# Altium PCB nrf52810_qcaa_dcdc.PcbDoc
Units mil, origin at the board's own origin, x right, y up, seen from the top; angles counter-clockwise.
Board outline 618 x 551 mil, 2 copper layers (Top Layer, Bottom Layer), stack 65.8 mil thick; 19 components, 31 nets, 72 pads, 43 vias.
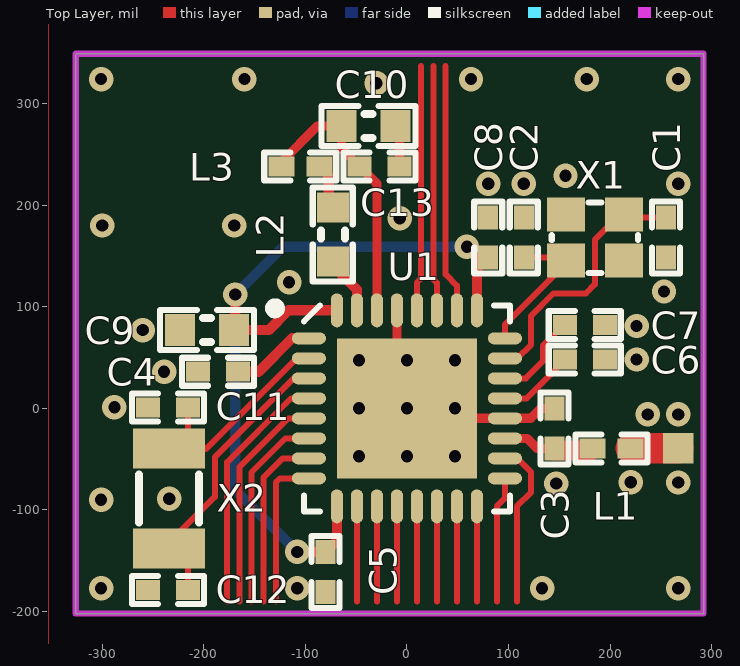
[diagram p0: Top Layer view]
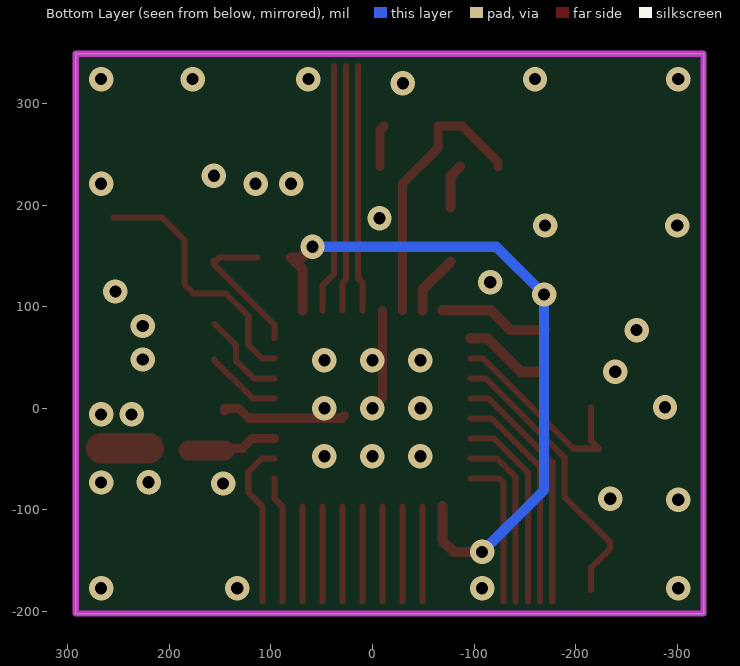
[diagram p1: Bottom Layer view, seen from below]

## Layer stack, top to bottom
Top Solder: solder mask 0.4, Solder Resist, Dk 3.5
Top Layer: signal copper 1.4
Dielectric1: core 63, FR-4, Dk 4.8
Bottom Layer: signal copper 1.4
Bottom Solder: solder mask 0.4, Solder Resist, Dk 3.5

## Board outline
-326,-202 292,-202 292,349 -326,349

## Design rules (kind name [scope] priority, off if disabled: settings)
AssemblyTestPointUsage [All] p0: scope1count=1 scope1_0_kind=Board scope1_0_value=Board scope2count=1 scope2_0_kind=Board scope2_0_value=Board commentlength=0
AssemblyTestpoint [All] p0: scope1count=1 scope1_0_kind=Board scope1_0_value=Board scope2count=1 scope2_0_kind=Board scope2_0_value=Board commentlength=0
Clearance Polygon [All] p0 off: scope1count=1 scope1_0_kind=Board scope1_0_value=Board scope2count=1 scope2_0_kind=Board scope2_0_value=Board commentlength=112 gap=10 // Protel DXP Scope 1 Expression Was: (InNamedPolygon('Top_Layer-GND')) or (InNamedPolygon('Bottom_Layer-GND'))
Clearance Polygon_ANT [All] p0 off: scope1count=1 scope1_0_kind=Board scope1_0_value=Board scope2count=1 scope2_0_kind=Net scope2_0_value=RF commentlength=112 gap=5 // Protel DXP Scope 1 Expression Was: (InNamedPolygon('Top_Layer-GND')) or (InNamedPolygon('Bottom_Layer-GND'))
Clearance [All] p0: scope1count=1 scope1_0_kind=Board scope1_0_value=Board scope2count=1 scope2_0_kind=Board scope2_0_value=Board commentlength=0 gap=6
Clearance Polygon_ANT [(InNamedPolygon('Top_Layer-GND')) or (InNamedPolygon('Bottom_Layer-GND')) vs InNet('RF')] p1: gap=5 ignorepadtopadclearanceinfootprint=FALSE except(0: Arc-Hole Track-Hole SMDPad-Hole THPad-Hole Via-Hole Fill-Hole Poly-Hole Region-Hole Text-Hole)
Clearance Polygon [(InNamedPolygon('Top_Layer-GND')) or (InNamedPolygon('Bottom_Layer-GND'))] p2: gap=10 ignorepadtopadclearanceinfootprint=FALSE except(0: Arc-Hole Track-Hole SMDPad-Hole THPad-Hole Via-Hole Fill-Hole Poly-Hole Region-Hole Text-Hole)
Clearance [All] p3: gap=6 ignorepadtopadclearanceinfootprint=FALSE except(0: Arc-Hole Track-Hole SMDPad-Hole THPad-Hole Via-Hole Fill-Hole Poly-Hole Region-Hole Text-Hole)
ComponentClearance [All] p0 off: scope1count=1 scope1_0_kind=Board scope1_0_value=Board scope2count=1 scope2_0_kind=Board scope2_0_value=Board commentlength=0 gap=10 collisioncheckmode=3
ComponentClearance [All] p1 off: gap=10 collisioncheckmode=3 verticalgap=10 showdistances=FALSE
DiffPairsRouting [All] p0: scope1count=1 scope1_0_kind=Board scope1_0_value=Board scope2count=1 scope2_0_kind=Board scope2_0_value=Board commentlength=0
FabricationTestPointUsage TestPointUsage [All] p0: scope1count=1 scope1_0_kind=Board scope1_0_value=Board scope2count=1 scope2_0_kind=Board scope2_0_value=Board commentlength=0 valid=0 allowmultiple=FALSE
FabricationTestPointUsage TestPointUsage [All] p1: valid=0 allowmultiple=FALSE
FabricationTestpoint Testpoint [All] p0: scope1count=1 scope1_0_kind=Board scope1_0_value=Board scope2count=1 scope2_0_kind=Board scope2_0_value=Board commentlength=0 side=3 testpointundercomponent=TRUE minsize=40 maxsize=100 preferedsize=60 minholesize=0 maxholesize=40 preferedholesize=32 testpointgrid=1
FabricationTestpoint Testpoint [All] p1: side=3 testpointundercomponent=TRUE minsize=40 maxsize=100 preferedsize=60 minholesize=0 maxholesize=40 preferedholesize=32 testpointgrid=1 allowsidetop=TRUE allowsidebottom=TRUE usegrid=TRUE gridtolerance=0.01
FanoutControl Fanout_Default [All] p0: scope1count=1 scope1_0_kind=Board scope1_0_value=Board scope2count=1 scope2_0_kind=Board scope2_0_value=Board commentlength=30 // Fanout_Default (Default Rule)
FanoutControl Fanout_Small [All] p0 off: scope1count=1 scope1_0_kind=Board scope1_0_value=Board scope2count=1 scope2_0_kind=Board scope2_0_value=Board commentlength=84 // Protel DXP Scope 1 Expression Was: (CompPinCount < 5)   Fanout_Small (Default Rule)
FanoutControl Fanout_SOIC [All] p0 off: scope1count=1 scope1_0_kind=Board scope1_0_value=Board scope2count=1 scope2_0_kind=Board scope2_0_value=Board commentlength=71 // Protel DXP Scope 1 Expression Was: IsSOIC   Fanout_SOIC (Default Rule)
FanoutControl Fanout_LCC [All] p0 off: scope1count=1 scope1_0_kind=Board scope1_0_value=Board scope2count=1 scope2_0_kind=Board scope2_0_value=Board commentlength=69 // Protel DXP Scope 1 Expression Was: IsLCC   Fanout_LCC (Default Rule)
FanoutControl Fanout_BGA [All] p0 off: scope1count=1 scope1_0_kind=Board scope1_0_value=Board scope2count=1 scope2_0_kind=Board scope2_0_value=Board commentlength=69 // Protel DXP Scope 1 Expression Was: IsBGA   Fanout_BGA (Default Rule)
Height [All] p0 off: scope1count=1 scope1_0_kind=Board scope1_0_value=Board scope2count=1 scope2_0_kind=Board scope2_0_value=Board commentlength=0
Height [All] p1 off: minheight=0 maxheight=1000 prefheight=500
HoleSize [All] p0: scope1count=1 scope1_0_kind=Board scope1_0_value=Board scope2count=1 scope2_0_kind=Board scope2_0_value=Board commentlength=0 absolutevalues=TRUE maxlimit=160 minlimit=12 maxpercent=80.000 minpercent=20.000
HoleSize [All] p1: absolutevalues=TRUE maxlimit=160 minlimit=12 maxpercent=80.000 minpercent=20.000
HoleToHoleClearance [All] p0: scope1count=1 scope1_0_kind=Board scope1_0_value=Board scope2count=1 scope2_0_kind=Board scope2_0_value=Board commentlength=0
LayerPairs [All] p0: scope1count=1 scope1_0_kind=Board scope1_0_value=Board scope2count=1 scope2_0_kind=Board scope2_0_value=Board commentlength=0 enforce=TRUE
MinimumAnnularRing [All] p0 off: scope1count=1 scope1_0_kind=Board scope1_0_value=Board scope2count=1 scope2_0_kind=Board scope2_0_value=Board commentlength=0 minimumring=6
MinimumAnnularRing [All] p1 off: minimumring=6
MinimumSolderMaskSliver [All] p0: scope1count=1 scope1_0_kind=Board scope1_0_value=Board scope2count=1 scope2_0_kind=Board scope2_0_value=Board commentlength=0
NetAntennae [All] p0: scope1count=1 scope1_0_kind=Board scope1_0_value=Board scope2count=1 scope2_0_kind=Board scope2_0_value=Board commentlength=0
PasteMaskExpansion [All] p0: scope1count=1 scope1_0_kind=Board scope1_0_value=Board scope2count=1 scope2_0_kind=Board scope2_0_value=Board commentlength=0 expansion=0
PlaneClearance [All] p0: scope1count=1 scope1_0_kind=Board scope1_0_value=Board scope2count=1 scope2_0_kind=Board scope2_0_value=Board commentlength=0 clearance=20
PlaneConnect [All] p0: scope1count=1 scope1_0_kind=Board scope1_0_value=Board scope2count=1 scope2_0_kind=Board scope2_0_value=Board commentlength=0 planeconnectstyle=Relief reliefexpansion=20 reliefentries=4 reliefconductorwidth=10 reliefairgap=10
PolygonConnect [All] p0: scope1count=1 scope1_0_kind=Board scope1_0_value=Board scope2count=1 scope2_0_kind=Board scope2_0_value=Board commentlength=0 connectstyle=Relief reliefconductorwidth=10 reliefentries=4 polygonreliefangle="90 Angle"
PolygonConnect PolygonConnect_1 [All] p0 off: scope1count=1 scope1_0_kind=Board scope1_0_value=Board scope2count=1 scope2_0_kind=Board scope2_0_value=Board commentlength=59 connectstyle=Direct reliefconductorwidth=10 reliefentries=4 polygonreliefangle="90 Angle" // Protel DXP Scope 1 Expression Was: isVia and innet(gnd)
PolygonConnect PolygonConnect_1 [isVia and innet(gnd)] p1: connectstyle=Direct reliefconductorwidth=10 reliefentries=4 polygonreliefangle="90 Angle" airgapwidth=10
PolygonConnect [All] p2: connectstyle=Relief reliefconductorwidth=10 reliefentries=4 polygonreliefangle="90 Angle" airgapwidth=10
RoutingCorners [All] p0: scope1count=1 scope1_0_kind=Board scope1_0_value=Board scope2count=1 scope2_0_kind=Board scope2_0_value=Board commentlength=0 cornerstyle=45-Degree minsetback=100 maxsetback=100
RoutingLayers [All] p0: scope1count=1 scope1_0_kind=Board scope1_0_value=Board scope2count=1 scope2_0_kind=Board scope2_0_value=Board commentlength=0 top layer=Automatic bottom layer=Automatic
RoutingPriority [All] p0: scope1count=1 scope1_0_kind=Board scope1_0_value=Board scope2count=1 scope2_0_kind=Board scope2_0_value=Board commentlength=0
RoutingTopology [All] p0: scope1count=1 scope1_0_kind=Board scope1_0_value=Board scope2count=1 scope2_0_kind=Board scope2_0_value=Board commentlength=0 topology=Shortest
RoutingVias [All] p0: scope1count=1 scope1_0_kind=Board scope1_0_value=Board scope2count=1 scope2_0_kind=Board scope2_0_value=Board commentlength=0 holewidth=16 width=32 viastyle="Through Hole" minholewidth=10 minwidth=10 maxholewidth=28 maxwidth=50
RoutingVias [All] p1: holewidth=16 width=32 viastyle="Through Hole" minholewidth=10 minwidth=10 maxholewidth=28 maxwidth=50
ShortCircuit [All] p0: scope1count=1 scope1_0_kind=Board scope1_0_value=Board scope2count=1 scope2_0_kind=Board scope2_0_value=Board commentlength=0 allowed=FALSE
SilkToBoardRegionClearance [All] p0: scope1count=1 scope1_0_kind=Board scope1_0_value=Board scope2count=1 scope2_0_kind=Board scope2_0_value=Board commentlength=0
SilkToSilkClearance [All] p0: scope1count=1 scope1_0_kind=Board scope1_0_value=Board scope2count=1 scope2_0_kind=Board scope2_0_value=Board commentlength=0
SilkToSolderMaskClearance SilkscreenOverComponentPads [All] p0 off: scope1count=1 scope1_0_kind=Board scope1_0_value=Board scope2count=1 scope2_0_kind=Board scope2_0_value=Board commentlength=44 // Protel DXP Scope 1 Expression Was: IsPad
SilkToSolderMaskClearance SilkscreenOverComponentPads [IsPad] p1: minsilkscreentomaskgap=10 clearancetoexposedcopper=TRUE
SolderMaskExpansion [All] p0: scope1count=1 scope1_0_kind=Board scope1_0_value=Board scope2count=1 scope2_0_kind=Board scope2_0_value=Board commentlength=0 expansion=3
SolderMaskExpansion [All] p1: expansion=3
UnRoutedNet [All] p0: scope1count=1 scope1_0_kind=Board scope1_0_value=Board scope2count=1 scope2_0_kind=Board scope2_0_value=Board commentlength=0
UnpouredPolygon [All] p0: scope1count=1 scope1_0_kind=Board scope1_0_value=Board scope2count=1 scope2_0_kind=Board scope2_0_value=Board commentlength=0
Width [All] p0: scope1count=1 scope1_0_kind=Board scope1_0_value=Board scope2count=1 scope2_0_kind=Board scope2_0_value=Board commentlength=0 maxlimit=100 minlimit=6 preferedwidth=6
Width [All] p1: maxlimit=100 minlimit=6 preferedwidth=6
24 further rules are at their usual default settings.

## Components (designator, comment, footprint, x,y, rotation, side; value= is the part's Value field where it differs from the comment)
C1 "12pF" CAPC1005X04L 255,168 r270 top
C2 "12pF" CAPC1005X04L 115,168 r90 top
C3 "0.8pF" CAPC1005X04L 145.32,-19.69 r270 top
C4 "100nF" CAPC1005X04L -186,36 r180 top
C5 "100nF" CAPC1005X04L -80,-161 r270 top
C6 "N.C." CAPC1005X04L 175,48 r180 top
C7 "100pF" CAPC1005X04L 175,82 r0 top
C8 "100nF" CAPC1005X04L 80,168 r90 top
C9 "4.7µF" CAPC1608X06L -197,77 r180 top
C10 "1.0µF" CAPC1608X06L -38,278 r180 top
C11 "12pF" CAPC1005X04L -235,1 r180 top
C12 "12pF" CAPC1005X04L -235,-179 r180 top
C13 "N.C." CAPC1005X04L -27,238 r0 top
L1 "3.9nH" INDC1005X04L 201.32,-39.69 r0 top
L2 "10µH" INDC1608X06L -73,171 r270 top
L3 "" INDC1005X04L -105,238 r0 top
U1 "nRF52810-QCAA" Nordic_QFN50P500X500X90-33N 0,0 r0 top locked
X1 "32MHz" BT-XTAL_2016 185,168 r180 top
X2 "32.768kHz" XTAL_3215 -234,-89 r270 top

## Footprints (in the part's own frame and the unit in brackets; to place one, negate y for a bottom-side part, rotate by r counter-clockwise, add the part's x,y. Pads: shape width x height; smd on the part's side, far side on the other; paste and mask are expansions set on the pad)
BT-XTAL_2016 [mm] "Crystal 2.0 x 1.6 mm"
  rect 0.95x0.85 smd: 1(-0.725,-0.575) 2(0.725,-0.575) 3(0.725,0.575) 4(-0.725,0.575)
  silkscreen extent -1.08,-0.88 1.08,0.88
CAPC1005X04L [mm] "Chip Capacitor, 2-Leads, Body 1.0x0.5mm, IPC High Density"
  rect 0.6x0.5 smd: 1(-0.5,0) 2(0.5,0)
  silkscreen extent -0.9,-0.35 0.9,0.35
CAPC1608X06L [mm] "Chip Capacitor, 2-Leads, Body 1.6x0.8mm, IPC High Density"
  rect 0.75x0.8 smd: 1(-0.675,0) 2(0.675,0)
  silkscreen extent -1.17,-0.5 1.17,0.5
INDC1005X04L [mm] "Chip Inductor, 2-Leads, Body 1.0x0.5mm, IPC High Density"
  rect 0.65x0.5 smd: 1(-0.475,0) 2(0.475,0)
  silkscreen extent -0.9,-0.35 0.9,0.35
INDC1608X06L [mm] "Chip Inductor, 2-Leads, Body 1.6x0.8mm, IPC High Density"
  rect 0.75x0.8 smd: 1(-0.675,0) 2(0.675,0)
  silkscreen extent -1.17,-0.5 1.17,0.5
Nordic_QFN50P500X500X90-33N [mm] "QFN32 5x5x0.85mm, 0.5mm pitch - Medium Density"
  oval 0.85x0.3 smd mask+0: 1(-2.45,1.75) 2(-2.45,1.25) 3(-2.45,0.75) 4(-2.45,0.25) 5(-2.45,-0.25) 6(-2.45,-0.75) 7(-2.45,-1.25) 8(-2.45,-1.75) 17(2.45,-1.75) 18(2.45,-1.25) 19(2.45,-0.75) 20(2.45,-0.25) 21(2.45,0.25) 22(2.45,0.75) 23(2.45,1.25) 24(2.45,1.75)
  oval 0.3x0.85 smd mask+0: 9(-1.75,-2.45) 10(-1.25,-2.45) 11(-0.75,-2.45) 12(-0.25,-2.45) 13(0.25,-2.45) 14(0.75,-2.45) 15(1.25,-2.45) 16(1.75,-2.45) 25(1.75,2.45) 26(1.25,2.45) 27(0.75,2.45) 28(0.25,2.45) 29(-0.25,2.45) 30(-0.75,2.45) 31(-1.25,2.45) 32(-1.75,2.45)
  rect 3.5x3.5 smd: 33(0,0)
  silkscreen extent -3.42,-2.57 2.57,2.62
XTAL_3215 [mm] "XTAL SMD 3.2 x 1.5 mm"
  rect 1x1.8 smd: 1(-1.25,0) 2(1.25,0)
  silkscreen extent -0.6,-0.75 0.6,0.75

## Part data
C1 C2 C11 C12: library part C0402-12p, "Capacitor, NP0, ±2%"
C3: library part C0402-0.8p, "Capacitor, NP0, ±5%"
C4 C5 C8: library part C0402-100n, "Capacitor, X7R, ±10%"
C6 C13: library part C0402-N.C., "Not mounted"
C7: library part C0402-100p, "Capacitor, NP0, ±5%"
C9: library part C0603-4µ7, "Capacitor, X5R, ±10%"
C10: library part C0603-1µ0, "Capacitor, X7R, ±10%"
L1: library part L0402-3n9, "High frequency chip inductor ±5%"
L2: library part L0603-10µ, "Chip inductor, IDC,min = 50 mA, ±20%"
L3: library part L0402-15n, "High frequency chip inductor ±10%"
U1: "Multi-protocol Bluetooth Low Energy, ANT and 2.4GHz proprietary system-on-chip"
X1: library part XTAL_SMD2016_32MHz_8pF_General, "XTAL SMD 2016, 32MHz, Cl=8pF, Total Tol: ±40ppm"
X2: library part XTAL_SMD3215_32.768kHz_9pF_General, "XTAL SMD 3215, 32.768kHz, Cl=9pF, Total Tol: ±50ppm"

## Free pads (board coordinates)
  rect 30x30 smd: 0(267.06,-39.43)

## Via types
v1: diameter 24, hole 12, Top Layer to Bottom Layer, tented both sides, 34 vias
v2: diameter 24, hole 12, Top Layer to Bottom Layer, tented bottom, 9 vias

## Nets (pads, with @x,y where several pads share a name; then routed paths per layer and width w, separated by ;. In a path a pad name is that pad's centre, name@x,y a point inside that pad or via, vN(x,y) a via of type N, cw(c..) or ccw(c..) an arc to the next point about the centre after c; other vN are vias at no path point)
DEC1: C4.1 U1.1 | length 83.5
  Top Layer w10: C4.1 -146,36 -113.1,68.9 U1.1
DEC2: C6.2 U1.21 | length 75.3
  Top Layer w6: U1.21 117.82,9.84 C6.2@155.98,48
DEC3: C7.1 U1.22 | length 89.9
  Top Layer w6: U1.22 117,29.53 134.19,46.72 134.19,61.87 C7.1@155.31,83
DEC4: C10.2 C13.1 L3.1 U1.30 | length 274.3
  Top Layer w9: L3.1 -123.7,242.3 -88,278 C10.2 -64.57,256.05 -29.53,221 U1.30
GND: C1.2 C2.2 C3.1 C4.2 C5.2 C6.1 C7.2 C8.2 C9.2 C10.1 C11.2 C12.2 C13.2 U1.20 U1.29 U1.33 X1.2 X1.4 | length 265.6
  Top Layer w9: C10.1 -7.31,273.89 C13.2 ; U1.29 -9.84,9.84 v2(0,0) ; U1.33@27.56,-6.89 30.51,-9.84 U1.20 121.89,-9.84 131.73,0 C3.1 ; C3.1@145.32,-2.35 C3.1@145.63,-2.35
  other v1: -301,-177 -108,-177 133,-177 267,-177 -301,-90 -234,-89 147,-74 220.32,-72.69 267,-73 237,-6 267,-6 -288,1 -239,36 226,48 -260,77 226,81 253,115 -116,124 -300,180 -170,180 -7,187 80,221 115,221 267,221 156,229 -30,320 -301,324 -160,324 63,324 177,324 267,324
  other v2: -47.24,-47.24 0,-47.24 47.24,-47.24 -47.24,0 47.24,0 -47.24,47.24 0,47.24 47.24,47.24
NetC3_2: C3.2 L1.1 U1.19 | length 88.6
  Top Layer w9: U1.19 118.11,-29.53 127.95,-39.37 C3.2 ; C3.2@145.32,-41.72 C3.2@145.63,-41.72
  Top Layer w20: C3.2@145.31,-41.53 L1.1@180.63,-41.53
NetL2_1: L2.1 L3.2 | length 44.3
  Top Layer w10: L3.2 -77,228.7 L2.1@-77,197.57
NetL2_2: L2.2 U1.31 | length 59.5
  Top Layer w10: L2.2@-77,144.43 -49.21,116.64 U1.31
P0.00/XL1: C11.1 U1.2 X2.1 | length 207.4
  Top Layer w6: C11.1 -215.32,-32.1 -223,-39.79 -197.68,-39.79 -108.68,49.21 U1.2
P0.01/XL2: C12.1 U1.3 X2.2 | length 282
  Top Layer w6: C12.1 -215.32,-156.9 X2.2 -234,-132 -189,-87 -189,-48.08 -111.39,29.53 U1.3
P0.04/AIN2: U1.4 | length 243.5
  Top Layer w6: -177,-190 -177,-53.05 -114.11,9.84 U1.4
P0.05/AIN3: U1.5 | length 220.5
  Top Layer w6: -165,-190 -165,-58.02 -116.82,-9.84 U1.5
P0.06: U1.6 | length 197.4
  Top Layer w6: -153,-190 -153,-62.99 -119.54,-29.53 U1.6
P0.09: U1.7 | length 174.3
  Top Layer w6: -141,-190 -141,-67.96 -122.25,-49.21 U1.7
P0.10: U1.8 | length 151.3
  Top Layer w6: -129,-190 -129,-72.93 -124.97,-68.9 U1.8
P0.12: U1.10 | length 93.5
  Top Layer w6: -49.21,-190 U1.10
P0.14: U1.11 | length 93.5
  Top Layer w6: -29.53,-190 U1.11
P0.15: U1.12 | length 93.5
  Top Layer w6: -9.84,-190 U1.12
P0.16: U1.13 | length 93.5
  Top Layer w6: 9.84,-190 U1.13
P0.18: U1.14 | length 93.5
  Top Layer w6: 29.53,-190 U1.14
P0.20: U1.15 | length 93.5
  Top Layer w6: 49.21,-190 U1.15
P0.21: U1.16 | length 93.5
  Top Layer w6: 68.9,-190 U1.16
P0.25: U1.26 | length 245.2
  Top Layer w6: 38,337 38,131.97 49.21,120.76 U1.26
P0.28/AIN4: U1.27 | length 242
  Top Layer w6: 26,337 26,127 29.53,123.47 U1.27
P0.30/AIN6: U1.28 | length 242.3
  Top Layer w6: U1.28 9.84,123.84 14,128 14,337
RF: L1.2 pad.0 | length 46.7
  Top Layer w30: L1.2@220.33,-39.43 pad.0
SWDCLK: U1.17 | length 124.4
  Top Layer w6: 88.58,-190 88.58,-96.46 96.46,-88.58 U1.17
SWDIO: U1.18 | length 164.4
  Top Layer w6: U1.18 108.68,-49.21 122.19,-62.72 122.19,-82.54 108.27,-96.46 108.27,-190
VDD_NRF: C5.1 C8.1 C9.1 U1.9 U1.25 U1.32 | length 830.6
  Top Layer w10: v1(-169,112) -169,78.43 C9.1 -136,77 -116.54,96.46 U1.32 ; v1(-108,-141.32) C5.1 -68.9,-130.21 U1.9 ; v1(59,159) 69.68,148.31 C8.1 68.9,137.21 U1.25
  Bottom Layer w10: v1(-108,-141.32) -169,-80.32 v1(-169,112) -122,159 v1(59,159)
XC1: C1.1 U1.23 X1.1 | length 258.2
  Top Layer w6: U1.23 108.68,49.21 122.19,62.72 122.19,91 144.19,113 176,113 185,122 185,166 206.68,187.68 C1.1
XC2: C2.1 U1.24 X1.3 | length 147.2
  Top Layer w6: U1.24 96.46,82.46 156.46,142.46 X1.3@156.46,142.52 ; C2.1@113,148.31 C2.1 150.66,148.31 X1.3@156.46,142.52 ; X1.3 X1.3@156.46,142.52

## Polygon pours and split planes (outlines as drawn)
GND on Top Layer "Top_Layer-GND" (solid, remove dead copper, pour order 1000): -353,410 -353,-266.19 363,-266.19 363,410 -353,410
GND on Bottom Layer "Bottom_Layer-GND" (solid, remove dead copper, pour order 1001): -373,400 -373,-266.19 394,-266.19 394,400 -373,400

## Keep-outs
Keep-Out Layer:
  the board outline again, w6

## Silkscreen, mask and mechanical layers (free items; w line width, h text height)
Mechanical 1:
  the board outline again, w6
